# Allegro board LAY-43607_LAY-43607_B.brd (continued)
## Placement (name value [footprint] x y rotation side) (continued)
R737  -  [RC0402_25]  104.58 22.62 0 top
R739  -  [RC0402_25]  20.79 77.81 90 top
R742  -  [RC0402_25]  26.4 76.47 180 top
R743  -  [RC0402_25]  93.7 58.84 90 bottom
R744  -  [RC0402_25]  99.51 62.01 0 top
R745  -  [RC0402_25]  105.19 82.44 0 bottom
R748  -  [RC0402_25]  87.49 91.71 90 bottom
R749  -  [RC0402_25]  88.38 91.71 90 bottom
R750  -  [RC0402_25]  89.59 86.07 270 bottom
R751  -  [RC0402_25]  88.71 86.07 270 bottom
R752  -  [RC0402_25]  90.22 103.93 90 bottom
R753  -  [RC0402_25]  90.22 102.06 270 bottom
R754  -  [RC0402_25]  90.73 91.78 90 bottom
R755  -  [RC0402_25]  91.62 91.78 90 bottom
R756  -  [RC0402_25]  91.44 86.07 270 bottom
R757  -  [RC0402_25]  90.47 86.07 270 bottom
R758  -  [RC0402_25]  87.86 86.06 270 bottom
R775  -  [RC0402_25]  20.74 62.29 90 top
R776  -  [RC0402_25]  21.8 62.32 90 top
R777  -  [RC0402_25]  21.52 68.81 0 top
R778  -  [RC0402_25]  21.57 67.97 0 top
R781  0  [RC0402_25]  32.07 68.29 0 top
R782  0  [RC0402_25]  32.07 67.36 0 top
R783  0  [RC0402_25]  32.07 66.49 0 top
R784  0  [RC0402_25]  32.07 65.63 0 top
R785  0  [RC0402_25]  33.34 64.53 0 top
R786  0  [RC0402_25]  33.34 63.64 0 top
R787  0  [RC0402_25]  28.39 59.72 0 top
R788  0  [RC0402_25]  28.39 58.83 0 top
R789  0  [RC0402_25]  33.34 62.65 0 top
R790  0  [RC0402_25]  33.34 61.76 0 top
R791  0  [RC0402_25]  25.17 60.68 270 top
R792  0  [RC0402_25]  24.33 60.7 270 top
R793  -  [RC0402_25]  100.7 85.84 90 bottom
R798  0  [RC0402_25]  21.91 51.21 90 top
R801  4.7K  [RC0402_25]  38.36 37.25 270 bottom
R803  4.7K  [RC0402_25]  37.2 37.23 90 bottom
R804  4.7K  [RC0402_25]  37.2 37.23 90 top
R805  4.7K  [RC0402_25]  38.36 37.25 90 top
R806  0  [RC0402_25]  38.44 39.49 270 top
R809  -  [RC0402_25]  103.08 24.66 90 bottom
R810  4.7K  [RC0402_25]  114.99 24.17 180 top
R811  4.7K  [RC0402_25]  103.01 32.4 90 bottom
R812  -  [RC0402_25]  111.12 13.34 0 bottom
R813  -  [RC0402_25]  111.12 14.61 0 bottom
R814  -  [RC0402_25]  83.43 45.81 0 bottom
R815  4.7K  [RC0402_25]  85.96 42.47 0 bottom
R816  -  [RC0402_25]  85.96 39.43 0 bottom
R817  4.7K  [RC0402_25]  85.96 40.44 0 bottom
R818  -  [RC0402_25]  85.96 41.46 0 bottom
R819  -  [RC0402_25]  50.69 61.43 90 top
R823  -  [RC0402_25]  52.18 62.37 180 top
R824  4.7K  [RC0402_25]  52.69 62.88 90 top
R825  -  [RC0402_25]  123.96 29.18 180 bottom
R828  -  [RC0402_25]  75.58 112.72 270 top
R829  -  [RC0402_25]  74.31 111.09 270 top
R830  -  [RC0402_25]  82.76 111.14 270 top
R831  -  [RC0402_25]  81.09 112.72 270 top
R832  -  [RC0402_25]  79.13 111.27 270 top
R833  -  [RC0402_25]  77.94 111.19 270 top
R834  -  [RC0402_25]  76.74 112.72 270 top
R837  0  [RC0402_25]  118.1 12.95 0 top
R840  -  [RC0402_25]  121.65 14.8 90 top
R841  -  [RC0402_25]  118.1 13.81 0 top
R843  -  [RC0402_25]  120.79 14.83 270 top
R849  -  [RC0402_25]  124.83 12.72 0 top
R850  -  [RC0402_25]  124.83 13.61 0 top
R851  -  [RC0402_25]  104.92 76.08 180 bottom
R852  -  [RC0402_25]  108.98 76.21 0 bottom
R853  -  [RC0402_25]  104.79 72.65 180 bottom
R854  -  [RC0402_25]  108.98 72.65 0 bottom
R855  -  [RC0402_25]  106.54 62.63 90 bottom
R856  -  [RC0402_25]  107.43 62.63 90 bottom
R857  -  [RC0402_25]  108.87 63.17 0 bottom
R858  -  [RC0402_25]  104.67 65.12 180 bottom
R859  -  [RC0402_25]  84.57 96.08 90 bottom
R860  -  [RC0402_25]  86.8 96.16 90 bottom
R861  -  [RC0402_25]  81.39 95.98 90 bottom
R862  -  [RC0402_25]  83.68 95.98 90 bottom
R863  -  [RC0201]  58.57 47 180 bottom
R864  -  [RC0402_25]  43.8 61.23 180 top
R865  10K  [RC0402_25]  20.25 57.95 180 bottom
R866  -  [RC0402_25]  20.76 59.35 90 bottom
R867  -  [RC0402_25]  46.8 65.56 90 top
R868  -  [RC0402_25]  45.9 62.52 180 top
R869  -  [RC0402_25]  90.28 112.54 270 bottom
R870  -  [RC0402_25]  48.75 58.31 180 top
R871  -  [RC0402_25]  48.75 59.33 180 top
R872  -  [RC0402_25]  48.25 58.82 90 bottom
R873  -  [RC0402_25]  83.43 41.62 0 bottom
R874  -  [RC0402_25]  48.75 60.22 180 top
R875  -  [RC0402_25]  48.75 61.1 180 top
R878  -  [RC0402_25]  103.16 87.16 270 bottom
R879  1.0K  [RC0402_25]  106.03 99.03 0 top
R880  -  [RC0402_25]  104 87.19 270 bottom
R881  17.4K  [RC0402_25]  103.13 92.07 90 top
R882  100K  [RC0402_25]  104.79 90.19 180 bottom
R883  -  [RC0402_25]  79.42 58.64 90 top
R885  -  [RC0402_25]  100.57 74.49 0 top
R886  -  [RC0402_25]  117.23 83.66 0 top
R887  0  [RC0402_25]  125.89 41.98 180 top
R888  -  [RC0402_25]  123.18 53.99 180 top
R889  -  [RC0402_25]  123.18 54.88 0 top
R890  -  [RES4_7P1X6P9_SM]  102.73 45.36 180 bottom
R893  0  [RC0402_25]  130.3 39.02 270 bottom
R894  0  [RC0402_25]  127.87 45.36 0 top
R895  0  [RC0402_25]  127.66 39.04 270 bottom
R896  0  [RC0402_25]  127.87 44.21 0 top
R897  0  [RC0402_25]  129.46 39.02 270 bottom
R898  0  [RC0402_25]  128.5 39.04 270 bottom
R899  0  [RC0402_25]  128.38 47.01 270 top
R900  -  [RC0402_25]  115.4 72.22 0 top
R901  -  [RC0402_25]  111.72 72.7 180 bottom
R902  -  [RC0402_25]  115.46 73.9 180 top
R903  -  [RC0402_25]  120.15 73.75 90 top
R904  0  [RC0402_25]  115.38 71.36 0 bottom
R905  -  [RC0402_25]  117.41 73.8 90 top
R906  -  [RC0402_25]  120.98 73.78 270 bottom
R907  -  [RC0402_25]  120.99 73.77 90 top
R908  -  [RC0402_25]  111.12 3.17 0 bottom
R909  -  [RC0402_25]  111.12 4.44 0 bottom
R910  -  [RC0402_25]  111.12 5.71 0 bottom
R911  -  [RC0402_25]  111.12 6.98 0 bottom
R912  -  [RC0402_25]  111.12 8.26 0 bottom
R913  -  [RC0402_25]  111.12 9.53 0 bottom
R914  -  [RC0402_25]  111.12 10.8 0 bottom
R915  -  [RC0402_25]  111.12 12.07 0 bottom
R916  -  [RC1206_OV]  100.59 117.31 270 bottom
R917  -  [RC1206_OV]  88.78 117.24 270 top
R920  0  [RC0402_25]  127.19 26.15 0 bottom
R921  -  [RC1206_OV]  114.92 10.56 90 bottom
R922  330 OHM  [RC0402_25]  36.38 46.84 270 top
R923  330 OHM  [RC0402_25]  40.9 35.4 180 top
R924  -  [RC0402_25]  98.21 70.6 270 bottom
R925  -  [RC0402_25]  115.28 100.88 270 bottom
R927  -  [RC0402_25]  71.36 70.25 90 top
R928  -  [RC0402_25]  77.56 84.32 180 top
R929  -  [RC0402_25]  72.25 70.22 90 bottom
R930  -  [RC0402_25]  72.25 70.22 270 top
R931  -  [RC0402_25]  77 78.91 270 bottom
R932  -  [RC0402_25]  69.96 84.13 90 top
R933  -  [RC0402_25]  69.07 84.13 90 top
R934  -  [RC0402_25]  70.47 70.25 90 top
R935  -  [RC0402_25]  69.45 70.25 90 top
R936  -  [RC0402_25]  75.3 70.27 90 top
R937  -  [RC0402_25]  73.52 84.13 270 top
R938  0  [RC0402_25]  70.47 70.25 270 bottom
R939  0  [RC0402_25]  77.56 83.3 0 top
R940  -  [RC0402_25]  99.35 66.46 90 top
R941  0  [RC0402_25]  76.57 102.96 90 top
R942  0  [RC0402_25]  75.73 102.96 90 top
R943  -  [RC0402_25]  65.14 73.55 180 top
R944  -  [RC0402_25]  122.51 14.8 270 top
R945  -  [RC0402_25]  35.83 65.28 180 top
R946  4.7K  [RC0402_25]  35.32 65.79 270 top
R947  0  [RC0402_25]  94.73 68.37 270 top
R948  -  [RC0402_25]  114.41 100.37 270 bottom
R953  0  [RC0402_25]  88.23 60.09 0 bottom
R954  -  [RC0402_25]  51.93 10.18 270 bottom
R955  -  [RC0402_25]  52.84 10.18 90 bottom
R956  -  [RC0402_25]  41.02 9.79 270 bottom
R957  -  [RC0402_25]  41.87 9.8 90 bottom
R958  -  [RC0402_25]  64.63 8.78 90 bottom
R959  -  [RC0402_25]  63.74 8.77 270 bottom
R960  -  [RC0402_25]  86.45 9.06 270 bottom
R961  -  [RC0402_25]  87.28 9.03 90 bottom
R962  -  [RC0402_25]  76.15 8.77 90 bottom
R963  -  [RC0402_25]  75.3 8.77 270 bottom
R964  -  [RC0201]  64.63 40.14 90 bottom
S1  -  [SW_DIP20_10POS_SM]  107.81 8.91 90 top
SW6  -  [SW2_4P45_4X3_SM]  129.68 36.9 180 top
TP94  5006  [TP_TH_063]  129.86 50.69 0 top
TP95  5006  [TP_TH_063]  88.5 82.19 0 top
TP116  -  [TP_PTH]  120.58 54.02 0 top
TP117  -  [TP_PTH]  121.4 55.9 0 top
TP126  -  [TPAD_020]  91.3 45.23 0 top
TP127  -  [TPAD_020]  19.38 77.73 0 top
TP128  -  [TP_PTH]  38.24 44.49 180 bottom
TP129  -  [TP_PTH]  38.24 46.65 180 bottom
TP130  -  [TP_PTH]  38.24 48.81 180 bottom
TP139  -  [TP_PTH]  40.65 30.17 0 top
TP140  -  [TP_PTH]  36.9 30.92 0 top
TP141  -  [TP_PTH]  38.93 31.37 0 top
TP142  -  [TPAD_020]  117.44 24.03 0 top
TVS1  SESD0402X1BN  [DIODE_BIDIR_0402]  77.73 116.76 180 top
U1  -  [QFN16_0P5_3X3_EP_4MP]  113.52 83.58 270 top
U14  -  [BGA780_0P8_23X23MM]  64.62 45.4 270 top
U15  -  [BGA96_0P8_8P1X14P1]  92.84 12.11 0 top
U16  MT40A512M16  [BGA96_0P8_8P1X14P1]  81.36 12.11 0 top
U17  -  [BGA96_0P8_8P1X14P1]  58.4 12.11 0 top
U18  -  [BGA96_0P8_8P1X14P1]  46.92 12.11 0 top
U24  -  [SOT-363_0P65_SMT]  90.26 59.29 0 top
U28  -  [SO8_1P27_4X5]  98.06 58.74 0 top
U35  74LVC2T45DC  [SSOP8_DCU]  73.65 99.08 180 top
U36  -  [SSOP8_DCU]  82.54 99.08 180 top
U37  -  [SSOP8_DCU]  76.44 99.08 0 top
U38  -  [XSON7_0P5_2P2X1P2]  76.13 110.35 90 top
U39  -  [XSON7_0P5_2P2X1P2]  80.96 110.38 90 top
U40  -  [WLCSP12_0P4_1P38X1P68MM_SMDP]  111.59 92.47 180 top
U42  PRTR5V0U2AX  [SOT143B]  103.34 111.93 90 bottom
U44  -  [XSON10_0P5_1P1X2P6MM]  96.17 95.67 90 bottom
U50  -  [QFN40_0P5_6X6_2P6EP]  26.83 65.09 270 top
U54  -  [WLCSP6_0P5_0P98X1P48]  118.58 19.7 0 top
U55  -  [SOT-363_0P65_SMT]  121.17 22.98 0 bottom
U56  -  [SC70-5]  121.22 25.76 90 top
U58  74AUP1G09GW  [SC70-5]  17.56 57.29 270 bottom
U60  -  [SC70-5]  17.61 59.91 270 bottom
U62  -  [SC70-5]  46.61 64.87 90 bottom
U114  -  [SC70-5]  121.22 25.76 90 bottom
U123  -  [AQFN138_0P65_12X12_EP]  41.64 76.6 180 top
U522  -  [VFBGA63_0P8_9X11]  109.84 23.39 270 bottom
U523  PCF2129AT  [SO20_1P27_7P6X12P95]  22.16 78.38 0 bottom
U524  -  [SO8_1P27_4X5]  102.48 81.78 0 top
U525  -  [TSSOP16]  89.2 88.81 90 top
U527  -  [SC70-5]  89.39 89.29 270 bottom
U530  -  [SC70-5]  100.66 87.05 180 top
U532  -  [SO16W]  107.74 28.62 0 top
U533  -  [SC70-5]  121.14 28.52 90 bottom
U534  -  [SC70-5]  120.89 17.8 180 bottom
U535  -  [SC70-5]  100.44 70.25 270 bottom
U536  -  [QFN20_3X3MM_B]  121.55 11.52 90 top
U537  PRTR5V0U2AX  [SOT143B]  118.98 8.78 270 bottom
U538  -  [TSSOP8_A]  106.82 64.14 180 top
U539  -  [SSOP8_DCU]  79.44 99.08 180 top
U540  -  [SSOP8_DCU]  85.53 99.1 180 top
U543  PUSB3AB6  [XSON7_0P5_2P2X1P2]  16.99 108.42 180 bottom
U544  PUSB3AB6  [XSON7_0P5_2P2X1P2]  17.03 98.26 180 bottom
U545  PUSB3AB6  [XSON7_0P5_2P2X1P2]  17.05 93.19 180 bottom
U546  -  [SC70-5]  44.82 61.87 270 bottom
U547  -  [SC70-5]  100.44 67.45 90 bottom
U548  -  [XSON_8P]  87.21 111.88 90 top
U549  -  [SSOP8_DCU]  100.62 64.07 270 top
U550  NX5P3090UK  [WLCSP12_0P4_1P38X1P68MM_SMDP]  104.89 92.17 180 top
U551  -  [SC70-5]  103.29 87.06 0 top
U552  PRTR5V0U2AX  [SOT143B]  99.22 99.18 270 top
U553  -  [XSON10_0P5_1P1X2P6MM]  100.65 95.67 90 bottom
U554  -  [UQFN10_0P4_1P45X1P85]  102.6 77.84 90 top
U555  -  [SSOP8_DCU]  100.56 74.01 0 bottom
U557  -  [BGA42_0P8_5X6]  119.75 45.36 270 top
U558  INA220AIDGST  [MSOP_10_0P5_3X3]  128.26 55.01 180 top
U560  -  [QFN24_4X4MM_4EP]  118.73 69.11 0 top
U561  -  [QFN56_0P5_8P1X8P1_EP5P1]  70.85 77.51 0 top
U562  -  [SC70-5]  121.14 28.52 90 top
U563  PUSB3AB6  [XSON7_0P5_2P2X1P2]  126.98 13.72 180 top
U564  PUSB3AB6  [XSON7_0P5_2P2X1P2]  125.87 22.9 180 bottom
U565  -  [BGA96_0P8_8P1X14P1]  69.88 12.11 0 top
U566  -  [SC70-5]  92.57 66.06 270 top

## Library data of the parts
BH5-BH10 = MOUNT_HOLE
BT3 = BATTERY_SKT_3V
C5 C27 C119 C120 C180 C288 C1331 C1337 C1338 C1346 = CAP_POL
C12 C14 C18-C22 C24-C26 C28 C30-C32 C36 C113 C125 C128 C151 C155 C159 C161 C166-C176 C230 C234 C235 C239 C240 C244 C245 C249 C254 C275 C279-C287 C289 C296 C297 C386 C388 C410 C431 C437 C457 C459 C1271-C1273 C1277 C1280 C1298 C1304 C1310 C1313 C1320 C1323 C1324 C1329 C1330 C1332 C1333 C1339-C1345 C1347 C1348 C1354 C1357 C1360 C1434-C1436 C1438 C1439 C1441 C1454-C1463 C1467-C1472 C1475 C1476 C1481 C1489-C1494 C1520 C1521 C1524 C1525 C1530 C1531 C1533 C1534 C1536 C1537 C1540 C1545 C1547-C1550 C1581 C1587 = CAP_NP
C29 = CAP_NP: tolerance: 20%; room: 12VIN
C114-C116 C118 C127 C252 C277 C1586 = CAP_NP: room: VDD_GVDD_PS
C122 C1139-C1142 C1150 C1151 C1156 C1157 = CAP_NP: tolerance: 5%
C126 C231 C233 C236 C238 C242 C243 C246 C248 C369 C408 C409 C438 C488 C668 C669 C847-C855 C1000 C1001 C1003-C1005 C1007-C1011 C1013 C1015-C1019 C1103 C1248 C1249 C1251 C1253 C1255 C1256 C1258 C1259 C1295 C1296 C1299 C1302 C1305 C1334 C1335 C1352 C1353 C1355 C1356 C1358 C1359 C1361 C1382 C1384 C1385 C1406 C1408 C1409 C1430 C1432 C1433 C1443-C1446 C1450-C1453 C1464 C1495 C1523 C1526 C1532 C1535 C1538 C1542 C1544 C1551-C1554 C1556 C1577 C1579 = CAP_NP: tolerance: 10%
C148 C149 C152 C153 C156 C157 C160 C162-C165 C181-C188 C193-C202 C206-C213 C219-C229 C258-C271 C290-C295 C298 C299 C301 C303-C324 C328 C329 C332-C334 C336-C338 C364-C367 C374 C375 C383 C384 C517-C524 C933-C936 C1349-C1351 C1362-C1380 C1386-C1404 C1410-C1428 C1557-C1575 = CAP_NP: Tolerance: 10%; User Part Number: 150-80059; tolerance: 10%
C189-C191 C203-C205 C214-C218 = CAP_NP: Tolerance: 10%; User Part Number: 150-75466; tolerance: 10%
C232 C237 C241 C247 = CAP_NP: Tolerance: TOLERANCE; User Part Number: 150-79701
C278 = CAP_NP: room: LED
C300 C302 C330 = CAP_NP: tolerance: 20%
C402 C403 C1584 C1585 = CAP_NP: room: DDR_DIMM
C449-C454 C463 C464 C487 C489 C492 C493 C497 C498 C905 C1297 C1306-C1309 C1314-C1319 C1325-C1328 C1555 C1582 C1583 = CAP_NP: Tolerance: TOLERANCE; User Part Number: 150-80059
C458 C1321 = CAP_NP: room: USB2
C460 C1322 = CAP_NP: room: VTT_VREF_PS
C693 C787-C789 C798 C1020 C1274-C1276 C1278 C1437 C1440 C1442 = CAP_NP: tolerance: 5%; room: RS232
C729 C772 C1021-C1024 C1143-C1149 C1152-C1155 = CAP_NP: tolerance: 10%; room: PEX_SLOTS123_REFCLK
C1104 = CAP_NP: room: PS_DDR1_2_VTT
C1166 C1168 C1293 C1294 C1546 = CAP_NP: Tolerance: TOLERANCE; User Part Number: 150-79474
C1174 C1282 C1283 C1447-C1449 C1465 C1466 = CAP_NP: tolerance: 10%; room: SDHC
D2 D4 D508 D510 D511 = LED
D6 = ZDIODE
D509 = LED_QUAD_GRN
F2 = FUSE_RST
FL2 FL31 FL32 = EMIFILTER_CC
FL3-FL5 FL7 FL8 FL28-FL30 = NFM18PC225B1A3: room: DUT_CLOSE
FL18 FL19 FL22 = NFM18PC225B1A3
J1 = DC_POWER_JACK_063BH
J8 J9 J11-J14 J72 J74 J75 = CONN_HDR_2X1
J15 = CONN_HDR_5X2
J46 J52 = CON_67_FEMALE_RA
J55 = CON8_SDCARD_DETECT
J56 J57 J66 = CONN_HDR_8X1
J58 = ZX62RD-AB-5P8_USB_MICROAB
J60 = CONN_HDR_6X1
J63-J65 = CONN_HDR_3X1
J67 = CONN_HDR_10X2
J70 = GSB311231HR_USB18P
J73 = HDR-1X4
L2 = CHOKE_4P
L9 L516 L531-L533 L535-L537 = INDUCTOR
L11 L514 = NFE31P: tolerance: 50%
L56 = INDUCTOR_FERRITE: tolerance: 25%
L515 = INDUCTOR: tolerance: 20%
P1 P2 = RJ45_MAG_2X1_LED
Q3 = MOSFET_N
Q4 = NMOSFET_3P_ESD_DIODE
R5 R10 = RES: room: DDR_PS
R6 R15 R887 R899 R904 R938 R939 = RES: tolerance: 5%; room: VDD_GVDD_PS
R7 R11 R13 R33 R36 R52 R55 R56 R59 R60 R64 R66 R67 R82-R84 R91-R98 R100-R107 R111-R138 R140-R144 R157 R158 R160 R161 R167-R172 R177 R185-R187 R191 R192 R202-R205 R228 R239 R241-R245 R248 R249 R257-R261 R277 R298 R299 R301-R305 R355 R409 R412 R473 R474 R558 R560 R643-R659 R661-R663 R666-R669 R737 R739 R742-R745 R748-R758 R775-R778 R793 R801 R803-R805 R809-R819 R823-R825 R828-R834 R840 R841 R843 R849-R875 R878-R883 R885 R886 R888 R889 R900-R903 R905-R917 R921-R925 R927-R937 R940 R943-R946 R948 R954-R964 = RES
R25 R62 R188 R255 R401 R471 R660 R781-R792 R798 R806 R837 R893-R898 R920 R941 R942 R947 R953 = RES: signal model: RES_RC0402_25_DISCRETE_0.4MM__7_0
R890 = RES_4PIN
S1 = SW_DIP-10
SW6 = SW2P_SPST
TP94 TP95 = TEST_POINT: room: CS
TP116 TP117 TP126-TP130 TP139-TP142 = TestLoop
TVS1 = DIODE_TVS_BIDIR
U1 = LT8609S_16P_EP
U14 = LS1043_1046_SS
U15-U18 U565 = MT40A512M16JY_BGA96
U24 = 74AUP2G07GW
U28 = SA56004ED_SO8
U35-U37 U539 U540 U549 U555 = 74LVC2T45DC_8P
U38 U39 U543-U545 U563 U564 = PUSB3AB6
U40 U550 = NX5P3090UK_WLCSP12
U42 U537 U552 = PRTR5V0U2AX: room: USB1
U44 U553 = DIODE_ESD_4CH_PUSB3AB4
U50 = Si5332FD10253-GM2_QFN40
U54 = ADM8611_WLCSP_6P
U55 = 74AUP1G11GW
U56 U114 U527 U533 = 74AUP1G07GW
U58 U60 U62 U534 U546 U547 U562 = GATE_AND_SGL
U123 = VSC8514_QFN_138P_A
U522 = S34MS04G200BH_BGA63P
U523 = PCF2129AT_SO_20P: room: I2C1_CH3
U524 = CAT24C04_SO8
U525 = PCA9546_16P
U530 U535 U551 U566 = NC7SZ14
U532 = MT25QU512ABB8ESF_SO16W
U536 = CP2102N_QFN20
U538 = PCA9510ADP_8P
U548 = NTB0102_8P
U554 = NX3DV42GU_XQFN_10P_A
U557 = LTC7150_BGA42
U558 = INA220AIDGST: room: I2C1_CH2
U560 = LT8642SEV_LQFN24
U561 = PC33PF8100A0ES_QFN56

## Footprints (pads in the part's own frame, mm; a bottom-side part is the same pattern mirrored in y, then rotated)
8X10P8
  rect 4.191x2.21 smd: 1(-3.645,0) 2(3.645,0)
AQFN138_0P65_12X12_EP
  rect 4.902x4.902 smd: 139(-0.325,0.65)
  round 0.737 smd: A1(5.45,-5.45) A4(5.45,5.45) A5(-5.45,5.45) A6(-5.45,-5.45)
  round 0.33 smd: A2(5.626,1.3) A3(5.626,1.95) A8(-0.325,-5.301) A9(0.325,-5.301) B1(4.976,-1.625) B2(4.976,-0.975) B3(4.976,0.325) B4(4.976,0.975) B5(4.976,1.625) B6(4.977,2.925) B8(4.976,4.225) B9(-5.627,3.575) B10(-5.627,2.925) B11(-5.627,0.975) B12(-5.627,0.325) B15(-2.6,-4.651) B16(-1.95,-4.651) B17(-1.3,-4.651) B20(1.3,-4.651) C1(4.326,-3.25) C2(4.326,-1.95) C4(4.326,-0.65) C5(4.326,0) C6(4.326,1.3) C7(4.326,1.95) C8(4.326,2.6) C9(4.326,3.25) C10(4.326,4.55) C11(4.225,5.302) C12(2.275,5.302) C13(1.625,5.302) C14(-4.977,4.55) C15(-4.977,3.9) C16(-4.977,3.25) C17(-4.977,2.6) C18(-4.977,1.3) C19(-4.977,0.65) C20(-4.977,-0.65) C21(-4.977,-1.95) C22(-4.977,-2.6) C23(-4.977,-3.25) C24(-4.225,-4.001) C25(-3.575,-4.001) C26(-2.925,-4.001) C27(-2.275,-4.001) C30(-0.325,-4.001) C34(2.275,-4.001) C35(2.925,-4.001) C36(4.225,-4.001) D1(3.676,-2.275) D2(3.676,-1.625) D3(3.676,-0.975) D4(3.676,-0.325) D5(3.676,0.325) D6(3.676,0.975) D7(3.676,1.625) D10(3.676,4.225) D11(2.6,4.652) D12(1.95,4.652) D13(0.65,4.652) D14(0,4.652) D15(-1.3,4.652) D16(-1.95,4.652) D17(-2.6,4.652) D18(-3.25,4.652) D19(-4.327,4.225) D20(-4.327,3.575) D22(-4.327,2.275) D23(-4.327,1.625) D24(-4.327,0.975) D25(-4.327,0.325) D26(-4.327,-0.325) D28(-4.327,-1.625) D29(-3.9,-3.351) D31(-2.6,-3.351) D32(1.3,-3.351) D34(2.6,-3.351) E1(3.026,-2.6) E2(3.026,-1.3) E5(3.026,0.65) E6(3.026,1.3) E7(3.026,1.95) E8(3.026,2.6) E9(3.026,3.25) E10(2.925,4.002) E12(1.625,4.002) E13(0.975,4.002) E15(-0.325,4.002) E17(-1.625,4.002) E19(-3.575,4.002) E21(-3.677,2.6) E22(-3.677,1.95) E23(-3.677,1.3) E24(-3.677,0.65) E25(-3.677,0) E27(-3.677,-1.3) E28(-3.677,-1.95) E29(-2.925,-2.701) E30(-2.275,-2.701) E31(-1.625,-2.701) E32(-0.975,-2.701) E33(-0.325,-2.701) E34(0.325,-2.701) E35(0.975,-2.701) E36(1.625,-2.701) E37(2.275,-2.701)
  oval 0.457x0.305 smd: A7(-0.975,-5.301) A10(0.975,-5.301) B19(0.65,-4.651) C28(-1.625,-4.001) C29(-0.975,-4.001) C31(0.325,-4.001) C32(0.975,-4.001) C33(1.625,-4.001) D35(3.25,-3.351) E11(2.275,4.002) E14(0.325,4.002) E16(-0.975,4.002)
  oval 0.305x0.457 smd: B7(4.976,3.575) C3(4.326,-1.3) D8(3.676,2.275) D9(3.676,2.925) D21(-4.327,2.925) E3(3.026,-0.65) E4(3.026,0) E20(-3.677,3.25)
  oval 0.305x0.584 smd: B13(-5.627,-0.975) B14(-5.627,-2.275) D27(-4.327,-0.975) E26(-3.677,-0.65)
  oval 0.584x0.305 smd: B18(-0.65,-4.651) D30(-3.25,-3.351) D33(1.95,-3.351) E18(-2.275,4.002)
BGA42_0P8_5X6
  round 0.406 smd: A1(-2,2.4) A2(-1.2,2.4) A3(-0.4,2.4) A4(0.4,2.4) A5(1.2,2.4) A6(2,2.4) B1(-2,1.6) B2(-1.2,1.6) B3(-0.4,1.6) B4(0.4,1.6) B5(1.2,1.6) B6(2,1.6) C1(-2,0.8) C2(-1.2,0.8) C3(-0.4,0.8) C4(0.4,0.8) C5(1.2,0.8) C6(2,0.8) D1(-2,0) D2(-1.2,0) D3(-0.4,0) D4(0.4,0) D5(1.2,0) D6(2,0) E1(-2,-0.8) E2(-1.2,-0.8) E3(-0.4,-0.8) E4(0.4,-0.8) E5(1.2,-0.8) E6(2,-0.8) F1(-2,-1.6) F2(-1.2,-1.6) F3(-0.4,-1.6) F4(0.4,-1.6) F5(1.2,-1.6) F6(2,-1.6) G1(-2,-2.4) G2(-1.2,-2.4) G3(-0.4,-2.4) G4(0.4,-2.4) G5(1.2,-2.4) G6(2,-2.4)
BGA96_0P8_8P1X14P1
  round 0.432 smd: A1(-3.2,6) A2(-2.4,6) A3(-1.6,6) A7(1.6,6) A8(2.4,6) A9(3.2,6) B1(-3.2,5.2) B2(-2.4,5.2) B3(-1.6,5.2) B7(1.6,5.2) B8(2.4,5.2) B9(3.2,5.2) C1(-3.2,4.4) C2(-2.4,4.4) C3(-1.6,4.4) C7(1.6,4.4) C8(2.4,4.4) C9(3.2,4.4) D1(-3.2,3.6) D2(-2.4,3.6) D3(-1.6,3.6) D7(1.6,3.6) D8(2.4,3.6) D9(3.2,3.6) E1(-3.2,2.8) E2(-2.4,2.8) E3(-1.6,2.8) E7(1.6,2.8) E8(2.4,2.8) E9(3.2,2.8) F1(-3.2,2) F2(-2.4,2) F3(-1.6,2) F7(1.6,2) F8(2.4,2) F9(3.2,2) G1(-3.2,1.2) G2(-2.4,1.2) G3(-1.6,1.2) G7(1.6,1.2) G8(2.4,1.2) G9(3.2,1.2) H1(-3.2,0.4) H2(-2.4,0.4) H3(-1.6,0.4) H7(1.6,0.4) H8(2.4,0.4) H9(3.2,0.4) J1(-3.2,-0.4) J2(-2.4,-0.4) J3(-1.6,-0.4) J7(1.6,-0.4) J8(2.4,-0.4) J9(3.2,-0.4) K1(-3.2,-1.2) K2(-2.4,-1.2) K3(-1.6,-1.2) K7(1.6,-1.2) K8(2.4,-1.2) K9(3.2,-1.2) L1(-3.2,-2) L2(-2.4,-2) L3(-1.6,-2) L7(1.6,-2) L8(2.4,-2) L9(3.2,-2) M1(-3.2,-2.8) M2(-2.4,-2.8) M3(-1.6,-2.8) M7(1.6,-2.8) M8(2.4,-2.8) M9(3.2,-2.8) N1(-3.2,-3.6) N2(-2.4,-3.6) N3(-1.6,-3.6) N7(1.6,-3.6) N8(2.4,-3.6) N9(3.2,-3.6) P1(-3.2,-4.4) P2(-2.4,-4.4) P3(-1.6,-4.4) P7(1.6,-4.4) P8(2.4,-4.4) P9(3.2,-4.4) R1(-3.2,-5.2) R2(-2.4,-5.2) R3(-1.6,-5.2) R7(1.6,-5.2) R8(2.4,-5.2) R9(3.2,-5.2) T1(-3.2,-6) T2(-2.4,-6) T3(-1.6,-6) T7(1.6,-6) T8(2.4,-6) T9(3.2,-6)
BGA780_0P8_23X23MM
  round 0.356 smd: A2(-10,10.8) A3(-9.2,10.8) A4(-8.4,10.8) A5(-7.6,10.8) A6(-6.8,10.8) A7(-6,10.8) A8(-5.2,10.8) A9(-4.4,10.8) A10(-3.6,10.8) A11(-2.8,10.8) A12(-2,10.8) A13(-1.2,10.8) A14(-0.4,10.8) A15(0.4,10.8) A16(1.2,10.8) A17(2,10.8) A18(2.8,10.8) A19(3.6,10.8) A20(4.4,10.8) A21(5.2,10.8) A22(6,10.8) A23(6.8,10.8) A24(7.6,10.8) A25(8.4,10.8) A26(9.2,10.8) A27(10,10.8) AA1(-10.8,-5.2) AA2(-10,-5.2) AA3(-9.2,-5.2) AA4(-8.4,-5.2) AA5(-7.6,-5.2) AA6(-6.8,-5.2) AA7(-6,-5.2) AA8(-5.2,-5.2) AA9(-4.4,-5.2) AA10(-3.6,-5.2) AA11(-2.8,-5.2) AA12(-2,-5.2) AA13(-1.2,-5.2) AA14(-0.4,-5.2) AA15(0.4,-5.2) AA16(1.2,-5.2) AA17(2,-5.2) AA18(2.8,-5.2) AA19(3.6,-5.2) AA20(4.4,-5.2) AA21(5.2,-5.2) AA22(6,-5.2) AA23(6.8,-5.2) AA24(7.6,-5.2) AA25(8.4,-5.2) AA26(9.2,-5.2) AA27(10,-5.2) AA28(10.8,-5.2) AB1(-10.8,-6) AB2(-10,-6) AB3(-9.2,-6) AB4(-8.4,-6) AB5(-7.6,-6) AB6(-6.8,-6) AB7(-6,-6) AB8(-5.2,-6) AB9(-4.4,-6) AB10(-3.6,-6) AB11(-2.8,-6) AB12(-2,-6) AB13(-1.2,-6) AB14(-0.4,-6) AB15(0.4,-6) AB16(1.2,-6) AB17(2,-6) AB18(2.8,-6) AB19(3.6,-6) AB20(4.4,-6) AB21(5.2,-6) AB22(6,-6) AB23(6.8,-6) AB24(7.6,-6) AB25(8.4,-6) AB26(9.2,-6) AB27(10,-6) AB28(10.8,-6) AC1(-10.8,-6.8) AC2(-10,-6.8) AC3(-9.2,-6.8) AC4(-8.4,-6.8) AC5(-7.6,-6.8) AC6(-6.8,-6.8) AC7(-6,-6.8) AC8(-5.2,-6.8) AC9(-4.4,-6.8) AC10(-3.6,-6.8) AC11(-2.8,-6.8) AC12(-2,-6.8) AC13(-1.2,-6.8) AC14(-0.4,-6.8) AC15(0.4,-6.8) AC16(1.2,-6.8) AC17(2,-6.8) AC18(2.8,-6.8) AC19(3.6,-6.8) AC20(4.4,-6.8) AC21(5.2,-6.8) AC22(6,-6.8) AC23(6.8,-6.8) AC24(7.6,-6.8) AC25(8.4,-6.8) AC26(9.2,-6.8) AC27(10,-6.8) AC28(10.8,-6.8) AD1(-10.8,-7.6) AD2(-10,-7.6) AD3(-9.2,-7.6) AD4(-8.4,-7.6) AD5(-7.6,-7.6) AD6(-6.8,-7.6) AD7(-6,-7.6) AD8(-5.2,-7.6) AD9(-4.4,-7.6) AD10(-3.6,-7.6) AD11(-2.8,-7.6) AD12(-2,-7.6) AD13(-1.2,-7.6) AD14(-0.4,-7.6) AD15(0.4,-7.6) AD16(1.2,-7.6) AD17(2,-7.6) AD18(2.8,-7.6) AD19(3.6,-7.6) AD20(4.4,-7.6) AD21(5.2,-7.6) AD22(6,-7.6) AD23(6.8,-7.6) AD24(7.6,-7.6) AD25(8.4,-7.6) AD26(9.2,-7.6) AD27(10,-7.6) AD28(10.8,-7.6) AE1(-10.8,-8.4) AE2(-10,-8.4) AE3(-9.2,-8.4) AE4(-8.4,-8.4) AE5(-7.6,-8.4) AE6(-6.8,-8.4) AE7(-6,-8.4) AE8(-5.2,-8.4) AE9(-4.4,-8.4) AE10(-3.6,-8.4) AE11(-2.8,-8.4) AE12(-2,-8.4) AE13(-1.2,-8.4) AE14(-0.4,-8.4) AE15(0.4,-8.4) AE16(1.2,-8.4) AE17(2,-8.4) AE18(2.8,-8.4) AE19(3.6,-8.4) AE20(4.4,-8.4) AE21(5.2,-8.4) AE22(6,-8.4) AE23(6.8,-8.4) AE24(7.6,-8.4) AE25(8.4,-8.4) AE26(9.2,-8.4) AE27(10,-8.4) AE28(10.8,-8.4) AF1(-10.8,-9.2) AF2(-10,-9.2) AF3(-9.2,-9.2) AF4(-8.4,-9.2) AF5(-7.6,-9.2) AF6(-6.8,-9.2) AF7(-6,-9.2) AF8(-5.2,-9.2) AF9(-4.4,-9.2) AF10(-3.6,-9.2) AF11(-2.8,-9.2) AF12(-2,-9.2) AF13(-1.2,-9.2) AF14(-0.4,-9.2) AF15(0.4,-9.2) AF16(1.2,-9.2) AF17(2,-9.2) AF18(2.8,-9.2) AF19(3.6,-9.2) AF20(4.4,-9.2) AF21(5.2,-9.2) AF22(6,-9.2) AF23(6.8,-9.2) AF24(7.6,-9.2) AF25(8.4,-9.2) AF26(9.2,-9.2) AF27(10,-9.2) AF28(10.8,-9.2) AG1(-10.8,-10) AG2(-10,-10) AG3(-9.2,-10) AG4(-8.4,-10) AG5(-7.6,-10) AG6(-6.8,-10) AG7(-6,-10) AG8(-5.2,-10) AG9(-4.4,-10) AG10(-3.6,-10) AG11(-2.8,-10) AG12(-2,-10) AG13(-1.2,-10) AG14(-0.4,-10) AG15(0.4,-10) AG16(1.2,-10) AG17(2,-10) AG18(2.8,-10) AG19(3.6,-10) AG20(4.4,-10) AG21(5.2,-10) AG22(6,-10) AG23(6.8,-10) AG24(7.6,-10) AG25(8.4,-10) AG26(9.2,-10) AG27(10,-10) AG28(10.8,-10) AH2(-10,-10.8) AH3(-9.2,-10.8) AH4(-8.4,-10.8) AH5(-7.6,-10.8) AH6(-6.8,-10.8) AH7(-6,-10.8) AH8(-5.2,-10.8) AH9(-4.4,-10.8) AH10(-3.6,-10.8) AH11(-2.8,-10.8) AH12(-2,-10.8) AH13(-1.2,-10.8) AH14(-0.4,-10.8) AH15(0.4,-10.8) AH16(1.2,-10.8) AH17(2,-10.8) AH18(2.8,-10.8) AH19(3.6,-10.8) AH20(4.4,-10.8) AH21(5.2,-10.8) AH22(6,-10.8) AH23(6.8,-10.8) AH24(7.6,-10.8) AH25(8.4,-10.8) AH26(9.2,-10.8) AH27(10,-10.8) B1(-10.8,10) B2(-10,10) B3(-9.2,10) B4(-8.4,10) B5(-7.6,10) B6(-6.8,10) B7(-6,10) B8(-5.2,10) B9(-4.4,10) B10(-3.6,10) B11(-2.8,10) B12(-2,10) B13(-1.2,10) B14(-0.4,10) B15(0.4,10) B16(1.2,10) B17(2,10) B18(2.8,10) B19(3.6,10) B20(4.4,10) B21(5.2,10) B22(6,10) B23(6.8,10) B24(7.6,10) B25(8.4,10) B26(9.2,10) B27(10,10) B28(10.8,10) C1(-10.8,9.2) C2(-10,9.2) C3(-9.2,9.2) C4(-8.4,9.2) C5(-7.6,9.2) C6(-6.8,9.2) C7(-6,9.2) C8(-5.2,9.2) C9(-4.4,9.2) C10(-3.6,9.2) C11(-2.8,9.2) C12(-2,9.2) C13(-1.2,9.2) C14(-0.4,9.2) C15(0.4,9.2) C16(1.2,9.2) C17(2,9.2) C18(2.8,9.2) C19(3.6,9.2) C20(4.4,9.2) C21(5.2,9.2) C22(6,9.2) C23(6.8,9.2) C24(7.6,9.2) C25(8.4,9.2) C26(9.2,9.2) C27(10,9.2) C28(10.8,9.2) D1(-10.8,8.4) D2(-10,8.4) D3(-9.2,8.4) D4(-8.4,8.4) D5(-7.6,8.4) D6(-6.8,8.4) D7(-6,8.4) D8(-5.2,8.4) D9(-4.4,8.4) D10(-3.6,8.4) D11(-2.8,8.4) D12(-2,8.4) D13(-1.2,8.4) D14(-0.4,8.4) D15(0.4,8.4) D16(1.2,8.4) D17(2,8.4) D18(2.8,8.4) D19(3.6,8.4) D20(4.4,8.4) D21(5.2,8.4) D22(6,8.4) D23(6.8,8.4) D24(7.6,8.4) D25(8.4,8.4) D26(9.2,8.4) D27(10,8.4) D28(10.8,8.4) E1(-10.8,7.6) E2(-10,7.6) E3(-9.2,7.6) E4(-8.4,7.6) E5(-7.6,7.6) E6(-6.8,7.6) E7(-6,7.6) E8(-5.2,7.6) E9(-4.4,7.6) E10(-3.6,7.6) E11(-2.8,7.6) E12(-2,7.6) E13(-1.2,7.6) E14(-0.4,7.6) E15(0.4,7.6) E16(1.2,7.6) E17(2,7.6) E18(2.8,7.6) E19(3.6,7.6) E20(4.4,7.6) E21(5.2,7.6) E22(6,7.6) E23(6.8,7.6) E24(7.6,7.6) E25(8.4,7.6) E26(9.2,7.6) E27(10,7.6) E28(10.8,7.6) F1(-10.8,6.8) F2(-10,6.8) F3(-9.2,6.8) F4(-8.4,6.8) F5(-7.6,6.8) F6(-6.8,6.8) F7(-6,6.8) F8(-5.2,6.8) F9(-4.4,6.8) F10(-3.6,6.8) F11(-2.8,6.8) F12(-2,6.8) F13(-1.2,6.8) F14(-0.4,6.8) F15(0.4,6.8) F16(1.2,6.8) F17(2,6.8) F18(2.8,6.8) F19(3.6,6.8) F20(4.4,6.8) F21(5.2,6.8) F22(6,6.8) F23(6.8,6.8) F24(7.6,6.8) F25(8.4,6.8) F26(9.2,6.8) F27(10,6.8) F28(10.8,6.8) G1(-10.8,6) G2(-10,6) G3(-9.2,6) G4(-8.4,6) G5(-7.6,6) G6(-6.8,6) G7(-6,6) G8(-5.2,6) G9(-4.4,6) G10(-3.6,6) G11(-2.8,6) G12(-2,6) G13(-1.2,6) G14(-0.4,6) G15(0.4,6) G16(1.2,6) G17(2,6) G18(2.8,6) G19(3.6,6) G20(4.4,6) G21(5.2,6) G22(6,6) G23(6.8,6) G24(7.6,6) G25(8.4,6) G26(9.2,6) G27(10,6) G28(10.8,6) H1(-10.8,5.2) H2(-10,5.2) H3(-9.2,5.2) H4(-8.4,5.2) H5(-7.6,5.2) H6(-6.8,5.2) H7(-6,5.2) H8(-5.2,5.2) H9(-4.4,5.2) H10(-3.6,5.2) H11(-2.8,5.2) H12(-2,5.2) H13(-1.2,5.2) H14(-0.4,5.2) H15(0.4,5.2) H16(1.2,5.2) H17(2,5.2) H18(2.8,5.2) H19(3.6,5.2) H20(4.4,5.2) H21(5.2,5.2) H22(6,5.2) H23(6.8,5.2) H24(7.6,5.2) H25(8.4,5.2) H26(9.2,5.2) H27(10,5.2) H28(10.8,5.2) J1(-10.8,4.4) J2(-10,4.4) J3(-9.2,4.4) J4(-8.4,4.4) J5(-7.6,4.4) J6(-6.8,4.4) J7(-6,4.4) J8(-5.2,4.4) J9(-4.4,4.4) J10(-3.6,4.4) J11(-2.8,4.4) J12(-2,4.4) J13(-1.2,4.4) J14(-0.4,4.4) J15(0.4,4.4) J16(1.2,4.4) J17(2,4.4) J18(2.8,4.4) J19(3.6,4.4) J20(4.4,4.4) J21(5.2,4.4) J22(6,4.4) J23(6.8,4.4) J24(7.6,4.4) J25(8.4,4.4) J26(9.2,4.4) J27(10,4.4) J28(10.8,4.4) K1(-10.8,3.6) K2(-10,3.6) K3(-9.2,3.6) K4(-8.4,3.6) K5(-7.6,3.6) K6(-6.8,3.6) K7(-6,3.6) K8(-5.2,3.6) K9(-4.4,3.6) K10(-3.6,3.6) K11(-2.8,3.6) K12(-2,3.6) K13(-1.2,3.6) K14(-0.4,3.6) K15(0.4,3.6) K16(1.2,3.6) K17(2,3.6) K18(2.8,3.6) K19(3.6,3.6) K20(4.4,3.6) K21(5.2,3.6) K22(6,3.6) K23(6.8,3.6) K24(7.6,3.6) K25(8.4,3.6) K26(9.2,3.6) K27(10,3.6) K28(10.8,3.6) L1(-10.8,2.8) L2(-10,2.8) L3(-9.2,2.8) L4(-8.4,2.8) L5(-7.6,2.8) L6(-6.8,2.8) L7(-6,2.8) L8(-5.2,2.8) L9(-4.4,2.8) L10(-3.6,2.8) L11(-2.8,2.8) L12(-2,2.8) L13(-1.2,2.8) L14(-0.4,2.8) L15(0.4,2.8) L16(1.2,2.8) L17(2,2.8) L18(2.8,2.8) L19(3.6,2.8) L20(4.4,2.8) L21(5.2,2.8) L22(6,2.8) L23(6.8,2.8) L24(7.6,2.8) L25(8.4,2.8) L26(9.2,2.8) L27(10,2.8) L28(10.8,2.8) M1(-10.8,2) M2(-10,2) M3(-9.2,2) M4(-8.4,2) M5(-7.6,2) M6(-6.8,2) M7(-6,2) M8(-5.2,2) M9(-4.4,2) M10(-3.6,2) M11(-2.8,2) M12(-2,2) M13(-1.2,2) M14(-0.4,2) M15(0.4,2) M16(1.2,2) M17(2,2) M18(2.8,2) M19(3.6,2) M20(4.4,2) M21(5.2,2) M22(6,2) M23(6.8,2) M24(7.6,2) M25(8.4,2) M26(9.2,2) M27(10,2) M28(10.8,2) N1(-10.8,1.2) N2(-10,1.2) N3(-9.2,1.2) N4(-8.4,1.2) N5(-7.6,1.2) N6(-6.8,1.2) N7(-6,1.2) N8(-5.2,1.2) N9(-4.4,1.2) N10(-3.6,1.2) N11(-2.8,1.2) N12(-2,1.2) N13(-1.2,1.2) N14(-0.4,1.2) N15(0.4,1.2) N16(1.2,1.2) N17(2,1.2) N18(2.8,1.2) N19(3.6,1.2) N20(4.4,1.2) N21(5.2,1.2) N22(6,1.2) N23(6.8,1.2) N24(7.6,1.2) N25(8.4,1.2) N26(9.2,1.2) N27(10,1.2) N28(10.8,1.2) P1(-10.8,0.4) P2(-10,0.4) P3(-9.2,0.4) P4(-8.4,0.4) P5(-7.6,0.4) P6(-6.8,0.4) P7(-6,0.4) P8(-5.2,0.4) P9(-4.4,0.4) P10(-3.6,0.4) P11(-2.8,0.4) P12(-2,0.4) P13(-1.2,0.4) P14(-0.4,0.4) P15(0.4,0.4) P16(1.2,0.4) P17(2,0.4) P18(2.8,0.4) P19(3.6,0.4) P20(4.4,0.4) P21(5.2,0.4) P22(6,0.4) P23(6.8,0.4) P24(7.6,0.4) P25(8.4,0.4) P26(9.2,0.4) P27(10,0.4) P28(10.8,0.4) R1(-10.8,-0.4) R2(-10,-0.4) R3(-9.2,-0.4) R4(-8.4,-0.4) R5(-7.6,-0.4) R6(-6.8,-0.4) R7(-6,-0.4) R8(-5.2,-0.4) R9(-4.4,-0.4) R10(-3.6,-0.4) R11(-2.8,-0.4) R12(-2,-0.4) R13(-1.2,-0.4) R14(-0.4,-0.4) R15(0.4,-0.4) R16(1.2,-0.4) R17(2,-0.4) R18(2.8,-0.4) R19(3.6,-0.4) R20(4.4,-0.4) R21(5.2,-0.4) R22(6,-0.4) R23(6.8,-0.4) R24(7.6,-0.4) R25(8.4,-0.4) R26(9.2,-0.4) R27(10,-0.4) R28(10.8,-0.4) T1(-10.8,-1.2) T2(-10,-1.2) T3(-9.2,-1.2) T4(-8.4,-1.2) T5(-7.6,-1.2) T6(-6.8,-1.2) T7(-6,-1.2) T8(-5.2,-1.2) T9(-4.4,-1.2) T10(-3.6,-1.2) T11(-2.8,-1.2) T12(-2,-1.2) T13(-1.2,-1.2) T14(-0.4,-1.2) T15(0.4,-1.2) T16(1.2,-1.2) T17(2,-1.2) T18(2.8,-1.2) T19(3.6,-1.2) T20(4.4,-1.2) T21(5.2,-1.2) T22(6,-1.2) T23(6.8,-1.2) T24(7.6,-1.2) T25(8.4,-1.2) T26(9.2,-1.2) T27(10,-1.2) T28(10.8,-1.2) U1(-10.8,-2) U2(-10,-2) U3(-9.2,-2) U4(-8.4,-2) U5(-7.6,-2) U6(-6.8,-2) U7(-6,-2) U8(-5.2,-2) U9(-4.4,-2) U10(-3.6,-2) U11(-2.8,-2) U12(-2,-2) U13(-1.2,-2) U14(-0.4,-2) U15(0.4,-2) U16(1.2,-2) U17(2,-2) U18(2.8,-2) U19(3.6,-2) U20(4.4,-2) U21(5.2,-2) U22(6,-2) U23(6.8,-2) U24(7.6,-2) U25(8.4,-2) U26(9.2,-2) U27(10,-2) U28(10.8,-2) V1(-10.8,-2.8) V2(-10,-2.8) V3(-9.2,-2.8) V4(-8.4,-2.8) V5(-7.6,-2.8) V6(-6.8,-2.8) V7(-6,-2.8) V8(-5.2,-2.8) V9(-4.4,-2.8) V10(-3.6,-2.8) V11(-2.8,-2.8) V12(-2,-2.8) V13(-1.2,-2.8) V14(-0.4,-2.8) V15(0.4,-2.8) V16(1.2,-2.8) V17(2,-2.8) V18(2.8,-2.8) V19(3.6,-2.8) V20(4.4,-2.8) V21(5.2,-2.8) V22(6,-2.8) V23(6.8,-2.8) V24(7.6,-2.8) V25(8.4,-2.8) V26(9.2,-2.8) V27(10,-2.8) V28(10.8,-2.8) W1(-10.8,-3.6) W2(-10,-3.6) W3(-9.2,-3.6) W4(-8.4,-3.6) W5(-7.6,-3.6) W6(-6.8,-3.6) W7(-6,-3.6) W8(-5.2,-3.6) W9(-4.4,-3.6) W10(-3.6,-3.6) W11(-2.8,-3.6) W12(-2,-3.6) W13(-1.2,-3.6) W14(-0.4,-3.6) W15(0.4,-3.6) W16(1.2,-3.6) W17(2,-3.6) W18(2.8,-3.6) W19(3.6,-3.6) W20(4.4,-3.6) W21(5.2,-3.6) W22(6,-3.6) W23(6.8,-3.6) W24(7.6,-3.6) W25(8.4,-3.6) W26(9.2,-3.6) W27(10,-3.6) W28(10.8,-3.6) Y1(-10.8,-4.4) Y2(-10,-4.4) Y3(-9.2,-4.4) Y4(-8.4,-4.4) Y5(-7.6,-4.4) Y6(-6.8,-4.4) Y7(-6,-4.4) Y8(-5.2,-4.4) Y9(-4.4,-4.4) Y10(-3.6,-4.4) Y11(-2.8,-4.4) Y12(-2,-4.4) Y13(-1.2,-4.4) Y14(-0.4,-4.4) Y15(0.4,-4.4) Y16(1.2,-4.4) Y17(2,-4.4) Y18(2.8,-4.4) Y19(3.6,-4.4) Y20(4.4,-4.4) Y21(5.2,-4.4) Y22(6,-4.4) Y23(6.8,-4.4) Y24(7.6,-4.4) Y25(8.4,-4.4) Y26(9.2,-4.4) Y27(10,-4.4) Y28(10.8,-4.4)
CC0201
  rect 0.47x0.381 smd: 1(-0.343,0) 2(0.343,0)
CC0402_25
  round 0.635 smd: 1(-0.508,0) 2(0.508,0)
CC0603_NFM18PC
  rect 0.61x0.61 smd: 1(-0.8,0) 3(0.8,0)
  rect 0.406x1.702 smd: 2(0,0)
CC0603_OV
  oval 0.889x1.143 smd: 1(-0.762,0) 2(0.762,0)
CC0805_OV
  oval 0.889x1.524 smd: 1(-0.965,0) 2(0.965,0)
CC1206_OV
  oval 1.016x1.778 smd: 1(-1.524,0) 2(1.524,0)
CC3528-21
  rect 1.905x2.286 smd: 1(-1.714,0) 2(1.714,0)
CC7343-31
  rect 2.134x2.997 smd: 1(-3.251,0) 2(3.251,0)
CC_NFM41P_1806
  rect 1.295x1.219 smd: 1(-2.375,0) 3(2.375,0)
  rect 1.524x1.016 smd: 2A(0,-0.813) 2B(0,0.813)
CCE6P8X6P8
  rect 3.556x1.651 smd: 1(-2.35,0) 2(2.35,0)
CON_1X8_SKT_2P54_TH
  rect 1.702x1.702 hole 1.016: 1(0,0)
  round 1.702 hole 1.016: 2(0,-2.54) 3(0,-5.08) 4(0,-7.62) 5(0,-10.16) 6(0,-12.7) 7(0,-15.24) 8(0,-17.78)
CON_18P_USB3_RA_TH
  rect 1.219x1.219 hole 0.711: 1(0,0)
  round 1.219 hole 0.711: 2(0,-2.5) 3(0,-4.5) 4(0,-7) 5(1.5,-7.5) 6(1.5,-5.5) 7(1.5,-3.5) 8(1.5,-1.5) 9(1.5,0.5) 10(3.2,0) 11(3.2,-2.5) 12(3.2,-4.5) 13(3.2,-7) 14(4.7,-7.5) 15(4.7,-5.5) 16(4.7,-3.5) 17(4.7,-1.5) 18(4.7,0.5)
  round 2.946 hole 2.311: S1(-2,3.07) S2(3.68,3.07) S3(3.68,-10.07) S4(-2,-10.07)
CON_67_0P5_22X7P75_RA
  rect 1.194x2.743 smd: (-10.35,3.125) (10.35,3.125)
  round 0.254 hole 1.092 unplated: (-10,-1.375)
  round 0.254 hole 1.6 unplated: (10,-1.375)
  rect 0.305x1.549 smd: 1(-9.25,3.9) 2(-9,-3.65) 3(-8.75,3.9) 4(-8.5,-3.65) 5(-8.25,3.9) 6(-8,-3.65) 7(-7.75,3.9) 8(-7.5,-3.65) 9(-7.25,3.9) 10(-7,-3.65) 11(-6.75,3.9) 12(-6.5,-3.65) 13(-6.25,3.9) 14(-6,-3.65) 15(-5.75,3.9) 16(-5.5,-3.65) 17(-5.25,3.9) 18(-5,-3.65) 19(-4.75,3.9) 20(-4.5,-3.65) 21(-4.25,3.9) 22(-4,-3.65) 23(-3.75,3.9) 32(-1.5,-3.65) 33(-1.25,3.9) 34(-1,-3.65) 35(-0.75,3.9) 36(-0.5,-3.65) 37(-0.25,3.9) 38(0,-3.65) 39(0.25,3.9) 40(0.5,-3.65) 41(0.75,3.9) 42(1,-3.65) 43(1.25,3.9) 44(1.5,-3.65) 45(1.75,3.9) 46(2,-3.65) 47(2.25,3.9) 48(2.5,-3.65) 49(2.75,3.9) 50(3,-3.65) 51(3.25,3.9) 52(3.5,-3.65) 53(3.75,3.9) 54(4,-3.65) 55(4.25,3.9) 56(4.5,-3.65) 57(4.75,3.9) 58(5,-3.65) 59(5.25,3.9) 60(5.5,-3.65) 61(5.75,3.9) 62(6,-3.65) 63(6.25,3.9) 64(6.5,-3.65) 65(6.75,3.9) 66(7,-3.65) 67(7.25,3.9) 68(7.5,-3.65) 69(7.75,3.9) 70(8,-3.65) 71(8.25,3.9) 72(8.5,-3.65) 73(8.75,3.9) 74(9,-3.65) 75(9.25,3.9)
CON_DCJACK_063BH_TH_RA
  oval 1.778x4.293 hole 1.016x3.531: (-4.5,7) (4.5,7)
  round 0.254 hole 1.6 unplated: (0,9)
  oval 4.801x1.778 hole 4.039x1.016: 1(0,0)
  oval 4.089x1.778 hole 3.327x1.016: 2(0,6)
CON_RJ45_2X1_TH_RA
  round 0.254 hole 3.251 unplated: (-0.545,-5.26) (12.545,-5.26)
  rect 1.397x1.397 hole 0.889: 1(0,0)
  round 1.397 hole 0.889: 2(2,0) 3(4,0) 4(6,0) 5(8,0) 6(10,0) 7(12,0) 8(1,2.54) 9(3,2.54) 10(5,2.54) 11(7,2.54) 12(9,2.54) 13(11,2.54) 14(0,10.41) 15(2,10.41) 16(4,10.41) 17(6,10.41) 18(8,10.41) 19(10,10.41) 20(12,10.41) 21(1,12.95) 22(3,12.95) 23(5,12.95) 24(7,12.95) 25(9,12.95) 26(11,12.95)
  round 1.524 hole 1.016: 27(0.055,-8.1) 28(2.085,-8.1) 29(9.915,-8.1) 30(11.945,-8.1) 31(0.545,16.76) 32(3.085,16.76) 33(8.915,16.76) 34(11.455,16.76)
  round 2.108 hole 1.6: S1(-2.395,6.53) S2(14.395,6.53) S3(-2.395,-9.83) S4(14.395,-9.83)
CON_SDCARD_95220
  rect 0.813x1.499 smd: 1(-1.94,3.267) 2(-0.84,2.867) 3(0.26,3.267) 4(1.36,3.468) 5(2.46,3.267) 6(3.56,3.468) 7(4.66,3.267) 8(5.76,3.267)
  rect 0.991x0.94 smd: 9(3.56,-7.368)
  rect 1.397x1.905 smd: SH1(6.6,6.187) SH2(-6.6,7.107)
  rect 1.295x1.422 smd: SH3(4.95,-7.092) SH4(-0.75,-7.092)
CON_TSM_20M_2P54_SM
  rect 1.27x3.683 smd: 1(-11.43,-2.475) 2(-11.43,2.475) 3(-8.89,-2.475) 4(-8.89,2.475) 5(-6.35,-2.475) 6(-6.35,2.475) 7(-3.81,-2.475) 8(-3.81,2.475) 9(-1.27,-2.475) 10(-1.27,2.475) 11(1.27,-2.475) 12(1.27,2.475) 13(3.81,-2.475) 14(3.81,2.475) 15(6.35,-2.475) 16(6.35,2.475) 17(8.89,-2.475) 18(8.89,2.475) 19(11.43,-2.475) 20(11.43,2.475)
CON_USB_5F_0P65_SM_RA_B
  rect 0.457x1.092 smd: 1(-1.3,4.67) 2(-0.65,4.67) 3(0,4.67) 4(0.65,4.67) 5(1.3,4.67)
  oval 1.194x2.108 hole 0.61x1.524: S1(-4.95,4.15) S2(4.95,4.15)
  oval 1.194x2.413 hole 0.61x1.803: S3(-4.95,0.15) S4(4.95,0.15)
DIODE_BIDIR_0402
  rect 0.559x0.61 smd: 1(-0.425,0) 2(0.425,0)
FUSE_3P4X1P8
  rect 0.991x1.803 smd: 1(-1.25,0) 2(1.25,0)
HDR1X2_50MIL
  rect 1.092x1.092 hole 0.711: 1(0,0)
  round 1.092 hole 0.711: 2(0,-1.27)
HDR102
  rect 1.524x1.524 hole 1.016: 1(0,0)
  round 1.524 hole 1.016: 2(0,-2.54)
HDR103
  rect 1.524x1.524 hole 1.016: 1(0,0)
  round 1.524 hole 1.016: 2(0,-2.54) 3(0,-5.08)
HDR106_TH_TSW
  rect 1.524x1.524 hole 1.041: 1(0,0)
  round 1.524 hole 1.041: 2(0,-2.54) 3(0,-5.08) 4(0,-7.62) 5(0,-10.16) 6(0,-12.7)
HDR205_10M_50_SM_K
  rect 0.737x2.794 smd: 1(-2.54,-2.032) 2(-2.54,2.032) 3(-1.27,-2.032) 4(-1.27,2.032) 5(0,-2.032) 6(0,2.032) 7(1.27,-2.032) 8(1.27,2.032) 9(2.54,-2.032) 10(2.54,2.032)
IND2_4P3SQ_XFL4020
  rect 0.965x3.404 smd: 1(-1.185,0) 2(1.185,0)
IND2_744308033
  rect 2.591x3.607 smd: 1(0,3.8) 2(0,-3.8)
IND2_XAL60XX_102
  rect 1.422x5.486 smd: 1(-2.019,0) 2(2.019,0)
IND4_7X13_SM
  rect 2.057x3.988 smd: 1(-2.25,6) 2(2.25,6) 3(2.25,-6) 4(-2.25,-6)
IND2520
  rect 0.914x2.21 smd: 1(-1.05,0) 2(1.05,0)
IND_0402
  round 0.635 smd: 1(-0.508,0) 2(0.508,0)
IND_NFE31P
  rect 0.991x1.803 smd: 1(-1.6,0) 3(1.6,0)
  rect 1.194x1.803 smd: 2(0,0)
JUMP1X4-6040
  rect 1.524x1.524 hole 1.016: 1(0,0)
  round 1.524 hole 1.016: 2(2.54,0) 3(5.08,0) 4(7.62,0)
JUMP1X8-6040
  rect 1.524x1.524 hole 1.016: 1(0,0)
  round 1.524 hole 1.016: 2(0,-2.54) 3(0,-5.08) 4(0,-7.62) 5(0,-10.16) 6(0,-12.7) 7(0,-15.24) 8(0,-17.78)
LED_0603
  rect 0.838x0.787 smd: A(-0.775,0) C(0.775,0)
LED_QUAD_2P54_TH
  rect 1.397x1.397 hole 0.889: 1(0,0)
  round 1.397 hole 0.889: 2(0,2.54) 3(-2.54,0) 4(-2.54,2.54) 5(-5.08,0) 6(-5.08,2.54) 7(-7.62,0) 8(-7.62,2.54)
MH_C256-165T
  round 6.502 hole 4.191: 1(0,0)
MSOP_10_0P5_3X3
  rect 1.372x0.279 smd: 1(-2.24,1) 2(-2.24,0.5) 3(-2.24,0) 4(-2.24,-0.5) 5(-2.24,-1) 6(2.24,-1) 7(2.24,-0.5) 8(2.24,0) 9(2.24,0.5) 10(2.24,1)
PMC_MECH_HOLE
  round 6.198 hole 3.2: 1(0,0)
QFN16_0P5_3X3_EP_4MP
  rect 0.381x0.381 smd: (-1.312,1.312) (-1.312,-1.312) (1.312,1.312) (1.312,-1.312)
  rect 0.711x0.254 smd: 1(-1.4,0.75) 2(-1.4,0.25) 3(-1.4,-0.25) 4(-1.4,-0.75) 9(1.4,-0.75) 10(1.4,-0.25) 11(1.4,0.25) 12(1.4,0.75)
  rect 0.254x0.711 smd: 5(-0.75,-1.4) 6(-0.25,-1.4) 7(0.25,-1.4) 8(0.75,-1.4) 13(0.75,1.4) 14(0.25,1.4) 15(-0.25,1.4) 16(-0.75,1.4)
  rect 1.448x1.448 smd: 17(0,0)
QFN20_3X3MM_B
  rect 0.305x0.305 smd: 1(-1.25,1.25) 6(-1.25,-1.25) 11(1.25,-1.25) 16(1.25,1.25)
  rect 0.889x0.305 smd: 2(-1.55,0.75) 3(-1.55,0.25) 4(-1.55,-0.25) 5(-1.55,-0.75) 12(1.55,-0.75) 13(1.55,-0.25) 14(1.55,0.25) 15(1.55,0.75)
  rect 0.305x0.889 smd: 7(-0.75,-1.55) 8(-0.25,-1.55) 9(0.25,-1.55) 10(0.75,-1.55) 17(0.75,1.55) 18(0.25,1.55) 19(-0.25,1.55) 20(-0.75,1.55)
  rect 1.803x1.803 smd: 21(0,0)
QFN24_4X4MM_4EP
  rect 0.381x0.381 smd: (-1.813,1.813) (-1.813,-1.813) (1.813,1.813) (1.813,-1.813)
  rect 0.711x0.254 smd: 1(-1.9,1.25) 2(-1.9,0.75) 3(-1.9,0.25) 4(-1.9,-0.25) 5(-1.9,-0.75) 6(-1.9,-1.25) 13(1.9,-1.25) 14(1.9,-0.75) 15(1.9,-0.25) 16(1.9,0.25) 17(1.9,0.75) 18(1.9,1.25)
  rect 0.254x0.711 smd: 7(-1.25,-1.9) 8(-0.75,-1.9) 9(-0.25,-1.9) 10(0.25,-1.9) 11(0.75,-1.9) 12(1.25,-1.9) 19(1.25,1.9) 20(0.75,1.9) 21(0.25,1.9) 22(-0.25,1.9) 23(-0.75,1.9) 24(-1.25,1.9)
  rect 1.118x1.118 smd: 25(-0.662,0.662) 26(0.662,0.662) 27(-0.662,-0.662) 28(0.662,-0.662)
QFN40_0P5_6X6_2P6EP
  oval 0.508x0.305 smd: 1(-2.76,2.25) 10(-2.76,-2.25) 21(2.76,-2.25) 30(2.76,2.25)
  rect 0.508x0.305 smd: 2(-2.76,1.75) 3(-2.76,1.25) 4(-2.76,0.75) 5(-2.76,0.25) 6(-2.76,-0.25) 7(-2.76,-0.75) 8(-2.76,-1.25) 9(-2.76,-1.75) 22(2.76,-1.75) 23(2.76,-1.25) 24(2.76,-0.75) 25(2.76,-0.25) 26(2.76,0.25) 27(2.76,0.75) 28(2.76,1.25) 29(2.76,1.75)
  oval 0.305x0.508 smd: 11(-2.25,-2.76) 20(2.25,-2.76) 31(2.25,2.76) 40(-2.25,2.76)
  rect 0.305x0.508 smd: 12(-1.75,-2.76) 13(-1.25,-2.76) 14(-0.75,-2.76) 15(-0.25,-2.76) 16(0.25,-2.76) 17(0.75,-2.76) 18(1.25,-2.76) 19(1.75,-2.76) 32(1.75,2.76) 33(1.25,2.76) 34(0.75,2.76) 35(0.25,2.76) 36(-0.25,2.76) 37(-0.75,2.76) 38(-1.25,2.76) 39(-1.75,2.76)
  rect 2.591x2.591 smd: 41(0,0)
QFN56_0P5_8P1X8P1_EP5P1
  rect 0.305x0.305 smd: (-3.73,3.73) (-3.73,-3.73) (3.73,3.73) (3.73,-3.73)
  oval 0.914x0.279 smd: 1(-3.922,3.25) 2(-3.922,2.75) 3(-3.922,2.25) 4(-3.922,1.75) 5(-3.922,1.25) 6(-3.922,0.75) 7(-3.922,0.25) 8(-3.922,-0.25) 9(-3.922,-0.75) 10(-3.922,-1.25) 11(-3.922,-1.75) 12(-3.922,-2.25) 13(-3.922,-2.75) 14(-3.922,-3.25) 29(3.922,-3.25) 30(3.922,-2.75) 31(3.922,-2.25) 32(3.922,-1.75) 33(3.922,-1.25) 34(3.922,-0.75) 35(3.922,-0.25) 36(3.922,0.25) 37(3.922,0.75) 38(3.922,1.25) 39(3.922,1.75) 40(3.922,2.25) 41(3.922,2.75) 42(3.922,3.25)
  oval 0.279x0.914 smd: 15(-3.25,-3.922) 16(-2.75,-3.922) 17(-2.25,-3.922) 18(-1.75,-3.922) 19(-1.25,-3.922) 20(-0.75,-3.922) 21(-0.25,-3.922) 22(0.25,-3.922) 23(0.75,-3.922) 24(1.25,-3.922) 25(1.75,-3.922) 26(2.25,-3.922) 27(2.75,-3.922) 28(3.25,-3.922) 43(3.25,3.922) 44(2.75,3.922) 45(2.25,3.922) 46(1.75,3.922) 47(1.25,3.922) 48(0.75,3.922) 49(0.25,3.922) 50(-0.25,3.922) 51(-0.75,3.922) 52(-1.25,3.922) 53(-1.75,3.922) 54(-2.25,3.922) 55(-2.75,3.922) 56(-3.25,3.922)
  rect 5.08x5.08 smd: 57(0,0)
RC0201
  rect 0.47x0.381 smd: 1(-0.343,0) 2(0.343,0)
RC0402_25
  round 0.635 smd: 1(-0.508,0) 2(0.508,0)
RC1206_OV
  oval 1.016x1.778 smd: 1(-1.524,0) 2(1.524,0)
RES4_7P1X6P9_SM
  rect 2.438x5.613 smd: 1(-2.48,-0.89) 4(2.48,-0.89)
  rect 2.438x0.889 smd: 2(-2.48,3.245) 3(2.48,3.245)
SC70-5
  rect 0.406x0.813 smd: 1(-0.65,-1.079) 2(0,-1.079) 3(0.65,-1.079) 4(0.65,1.079) 5(-0.65,1.079)
SKT_BAT_225X886_3V
  rect 1.651x1.651 hole 1.016: 1(0,0)
  round 1.651 hole 1.016: 2(10,0) 3(5,3.47)
SO8_1P27_4X5
  rect 1.6x0.61 smd: 1(-2.7,1.905) 2(-2.7,0.635) 3(-2.7,-0.635) 4(-2.7,-1.905) 5(2.7,-1.905) 6(2.7,-0.635) 7(2.7,0.635) 8(2.7,1.905)
SO16W
  rect 2.184x0.61 smd: 1(-4.826,4.445) 2(-4.826,3.175) 3(-4.826,1.905) 4(-4.826,0.635) 5(-4.826,-0.635) 6(-4.826,-1.905) 7(-4.826,-3.175) 8(-4.826,-4.445) 9(4.826,-4.445) 10(4.826,-3.175) 11(4.826,-1.905) 12(4.826,-0.635) 13(4.826,0.635) 14(4.826,1.905) 15(4.826,3.175) 16(4.826,4.445)
SO20_1P27_7P6X12P95
  rect 1.778x0.61 smd: 1(-4.738,5.715) 2(-4.738,4.445) 3(-4.738,3.175) 4(-4.738,1.905) 5(-4.738,0.635) 6(-4.738,-0.635) 7(-4.738,-1.905) 8(-4.738,-3.175) 9(-4.738,-4.445) 10(-4.738,-5.715) 11(4.738,-5.715) 12(4.738,-4.445) 13(4.738,-3.175) 14(4.738,-1.905) 15(4.738,-0.635) 16(4.738,0.635) 17(4.738,1.905) 18(4.738,3.175) 19(4.738,4.445) 20(4.738,5.715)
SOD123
  rect 1.016x1.27 smd: A(1.651,0) C(-1.651,0)
SOT23-40X40
  rect 1.016x1.016 smd: 1(-0.94,-1.003) 2(0.94,-1.003) 3(0,1.003)
SOT143B
  rect 0.991x0.61 smd: 1(-0.75,-1)
  rect 0.508x0.61 smd: 2(0.95,-1) 3(0.95,1) 4(-0.95,1)
SOT323_3
  rect 0.406x0.991 smd: 1(0.65,-1.06) 2(-0.65,-1.06) 3(0,1.06)
SOT-363_0P65_SMT
  rect 0.762x0.381 smd: 1(-1.085,0.65) 2(-1.085,0) 3(-1.085,-0.65) 4(1.085,-0.65) 5(1.085,0) 6(1.085,0.65)
SSOP8_DCU
  rect 0.279x1.219 smd: 1(-0.75,-1.499) 2(-0.25,-1.499) 3(0.25,-1.499) 4(0.75,-1.499) 5(0.75,1.499) 6(0.25,1.499) 7(-0.25,1.499) 8(-0.75,1.499)
SW2_4P45_4X3_SM
  rect 1.041x2.007 smd: 1(-2.225,0) 2(2.225,0)
SW_DIP20_10POS_SM
  rect 0.762x1.27 smd: 1(-5.725,-3.81) 2(-4.455,-3.81) 3(-3.185,-3.81) 4(-1.915,-3.81) 5(-0.635,-3.81) 6(0.635,-3.81) 7(1.905,-3.81) 8(3.175,-3.81) 9(4.445,-3.81) 10(5.715,-3.81) 11(5.715,3.81) 12(4.445,3.81) 13(3.175,3.81) 14(1.905,3.81) 15(0.635,3.81) 16(-0.635,3.81) 17(-1.915,3.81) 18(-3.185,3.81) 19(-4.455,3.81) 20(-5.725,3.81)
TP_PTH
  round 0.889 hole 0.457: 1(0,0)
TP_TH_063
  round 2.311 hole 1.6: 1(0,0)
TPAD_020
  round 0.508 smd: 1(0,0)
TSSOP8_A
  rect 1.448x0.457 smd: 1(-2.15,0.975) 2(-2.15,0.325) 3(-2.15,-0.325) 4(-2.15,-0.975) 5(2.15,-0.975) 6(2.15,-0.325) 7(2.15,0.325) 8(2.15,0.975)
TSSOP16
  rect 1.524x0.305 smd: 1(-3.048,2.276) 2(-3.048,1.626) 3(-3.048,0.975) 4(-3.048,0.325) 5(-3.048,-0.325) 6(-3.048,-0.975) 7(-3.048,-1.626) 8(-3.048,-2.276) 9(3.048,-2.276) 10(3.048,-1.626) 11(3.048,-0.975) 12(3.048,-0.325) 13(3.048,0.325) 14(3.048,0.975) 15(3.048,1.626) 16(3.048,2.276)
unnamed#2
  round 1.524 smd: (0,0)
unnamed#3
  round 1.626 hole 0.965: (0,0) (0,-5.08)
UQFN10_0P4_1P45X1P85
  rect 0.686x0.229 smd: 1(-0.527,0.2)
  rect 0.584x0.229 smd: 2(-0.578,-0.2) 6(0.578,-0.2) 7(0.578,0.2)
  rect 0.229x0.584 smd: 3(-0.4,-0.778) 4(0,-0.778) 5(0.4,-0.778) 8(0.4,0.778) 9(0,0.778) 10(-0.4,0.778)
VFBGA63_0P8_9X11
  round 0.356 smd: A1(-3.6,4.4) A2(-2.8,4.4) A9(2.8,4.4) A10(3.6,4.4) B1(-3.6,3.6) B9(2.8,3.6) B10(3.6,3.6) C3(-2,2.8) C4(-1.2,2.8) C5(-0.4,2.8) C6(0.4,2.8) C7(1.2,2.8) C8(2,2.8) D3(-2,2) D4(-1.2,2) D5(-0.4,2) D6(0.4,2) D7(1.2,2) D8(2,2) E3(-2,1.2) E4(-1.2,1.2) E5(-0.4,1.2) E6(0.4,1.2) E7(1.2,1.2) E8(2,1.2) F3(-2,0.4) F4(-1.2,0.4) F5(-0.4,0.4) F6(0.4,0.4) F7(1.2,0.4) F8(2,0.4) G3(-2,-0.4) G4(-1.2,-0.4) G5(-0.4,-0.4) G6(0.4,-0.4) G7(1.2,-0.4) G8(2,-0.4) H3(-2,-1.2) H4(-1.2,-1.2) H5(-0.4,-1.2) H6(0.4,-1.2) H7(1.2,-1.2) H8(2,-1.2) J3(-2,-2) J4(-1.2,-2) J5(-0.4,-2) J6(0.4,-2) J7(1.2,-2) J8(2,-2) K3(-2,-2.8) K4(-1.2,-2.8) K5(-0.4,-2.8) K6(0.4,-2.8) K7(1.2,-2.8) K8(2,-2.8) L1(-3.6,-3.6) L2(-2.8,-3.6) L9(2.8,-3.6) L10(3.6,-3.6) M1(-3.6,-4.4) M2(-2.8,-4.4) M9(2.8,-4.4) M10(3.6,-4.4)
WLCSP6_0P5_0P98X1P48
  round 0.254 smd: A1(-0.25,0.5) A2(0.25,0.5) B1(-0.25,0) B2(0.25,0) C1(-0.25,-0.5) C2(0.25,-0.5)
WLCSP12_0P4_1P38X1P68MM_SMDP
  round 0.254 smd: A1(-0.4,0.6) A2(0,0.6) A3(0.4,0.6) B1(-0.4,0.2) B2(0,0.2) B3(0.4,0.2) C1(-0.4,-0.2) C2(0,-0.2) C3(0.4,-0.2) D1(-0.4,-0.6) D2(0,-0.6) D3(0.4,-0.6)
XSON7_0P5_2P2X1P2
  rect 0.533x0.203 smd: 1(-0.415,0.75) 2(-0.415,0.25) 3(-0.415,-0.25) 4(-0.415,-0.75) 5(0.415,-0.5) 6(0.415,0) 7(0.415,0.5)
XSON10_0P5_1P1X2P6MM
  rect 0.711x0.254 smd: 1(-0.457,1) 2(-0.457,0.5) 3(-0.457,0) 4(-0.457,-0.5) 5(-0.457,-1) 6(0.457,-1) 7(0.457,-0.5) 8(0.457,0) 9(0.457,0.5) 10(0.457,1)
XSON_8P
  rect 0.305x0.61 smd: 1(-0.75,-0.417) 2(-0.25,-0.417) 3(0.25,-0.417) 4(0.75,-0.417) 5(0.75,0.417) 6(0.25,0.417) 7(-0.25,0.417) 8(-0.75,0.417)

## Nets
1V0_F104: C787.1 C851.1 C852.1 C853.1 C854.1 C855.1 C1454.1 C1455.1 C1475.1 C1476.1 C1495.1 FL19.1 L531.1 U123.E5 U123.E7 U123.E10 U123.E13 U123.E15 U123.E17 U123.E19 U123.E21 U123.E23 U123.E25 U561.3
1V0_QSG: C788.1 C1000.1 C1001.1 C1003.1 C1004.1 C1005.1 C1007.1 C1008.1 C1456.1 FL19.3(OUT_IN) U123.E1 U123.E11 U123.E14 U123.E16 U123.E28 U123.E30 U123.E32 U123.E34 U123.E36
1V35: C277.1 C1524.1 C1525.1 C1526.1 FL8.1 L533.1 U561.13
2V5: C160.1 C161.1 C369.1 C789.1 C1015.1 C1016.1 C1017.1 C1018.1 C1019.1 C1020.1 C1103.1 C1384.1 C1408.1 C1432.1 C1457.1 C1458.1 C1536.1 C1537.1 C1538.1 C1579.1 FL18.3(OUT_IN) FL22.1 L537.1 R651.1 R654.2 R657.2 R658.2 R659.2 R871.2 R872.2 U14.W6 U15.B1 U15.R9 U16.B1 U16.R9 U17.B1 U17.R9 U18.B1 U18.R9 U123.E3 U123.E4 U123.E6 U123.E8 U123.E9 U123.E12 U123.E18 U123.E20 U123.E22 U123.E24 U123.E26 U561.38 U565.B1 U565.R9
2V5_LED: C729.1 C1104.1 FL22.3(OUT_IN) P1.28 P1.29 P1.32 P1.33 P2.28 P2.29 P2.32 P2.33
2V5_QSG: C798.1 C1009.1 C1010.1 C1011.1 C1013.1 C1459.1 FL18.1 U123.E27 U123.E29 U123.E31 U123.E33 U123.E35 U123.E37
3V3: C278.1 C298.1 C299.1 C300.1 C301.1 C302.1 C438.1 C450.1 C452.1 C454.1 C488.1 C1174.1 C1255.1 C1256.1 C1258.1 C1259.1 C1271.1 C1272.1 C1282.1 C1283.1 C1298.1 C1299.1 C1302.1 C1304.1 C1305.1 C1307.1 C1309.1 C1310.1 C1313.1 C1315.1 C1316.1 C1319.1 C1327.1 C1334.1 C1337.1 C1338.1 C1339.1 C1340.1 C1341.1 C1434.1 C1435.1 C1443.1 C1444.1 C1445.1 C1446.1 C1447.1 C1448.1 C1449.1 C1450.1 C1451.1 C1452.1 C1453.1 C1464.1 C1465.1 C1466.1 C1470.1 C1481.1 C1489.1 C1490.1 C1491.1 C1492.1 C1493.1 C1494.1 C1542.1 C1544.1 C1547.1 C1548.1 C1549.1 C1555.1 D2.A D509.2 D509.4 D509.6 FL5.1 FL28.3(OUT_IN) FL30.3(OUT_IN) J46.2 J46.4 J46.72 J46.74 J52.2 J52.4 J52.72 J52.74 J55.4 J56.7 J66.1 J73.1 L516.2 R5.1 R10.1 R66.1 R245.1 R666.1 R667.1 R668.1 R669.2 R739.1 R742.2 R743.2 R744.2 R748.1 R749.1 R750.1 R751.1 R752.1 R753.1 R754.1 R755.1 R756.1 R757.1 R758.1 R777.1 R778.1 R801.2 R803.1 R804.1 R805.1 R828.1 R829.1 R830.1 R831.1 R832.1 R833.1 R834.1 R840.2 R843.1 R851.1 R852.1 R853.1 R854.1 R855.1 R856.1 R857.1 R858.2 R864.1 R869.1 R878.1 R900.1 R901.1 R904.1 R920.1 R922.2 R923.2 R927.1 R928.1 R929.1 R931.2 R934.1 R936.1 R940.1 R944.1 R946.1 TVS1.1 U14.N7 U14.P7 U14.R6 U24.5(VCC) U28.1(VDD) U35.1 U36.1 U37.8(VCCB) U54.A1(VCC) U523.20 U524.2 U524.8 U525.1 U525.2 U525.13 U525.16 U530.5 U535.5 U536.6 U536.7 U538.8(VCC) U539.1 U540.1 U547.5 U548.7(VCCB) U549.1 U551.5 U554.9(VCC) U555.1 U558.6 U561.4 U561.7 U561.8 U561.11 U561.17 U561.26 U561.27 U561.32 U561.35 U561.37 U561.50 U561.54 U562.5 U566.5
3V3_EN: R906.2 R907.1 U560.17
5V0: C19.2 C20.1 C21.1 C22.1 C457.1 C1320.1 C1329.1 J57.7 L515.2 R7.2 U40.B1 U40.B2 U40.C1(VINT3) U550.B1 U550.B2 U550.C1(VINT3)
12V0: C5.1 C12.1 C14.1 C30.1 C31.1 C32.1 C1330.1 C1345.1 C1587.1 FL2.1 FL31.1 FL32.1 J75.1 L2.2
12V0_FILTERED_PS_V1V0: C24.1 C25.1 C26.1 C27.1 C28.1 FL32.3(OUTPUT) R13.1 U557.C2 U557.C5 U557.C6 U557.D1 U557.D2 U557.D5 U557.D6
12V0_FILTERED_PS_V3V3: C1346.1 C1347.1 C1348.1 C1468.1 C1469.1 C1581.1 FL31.3(OUTPUT) R906.1 U560.4 U560.5 U560.6 U560.13 U560.14 U560.15(VIN6)
12V0_FILTERED_PS_V5V0: C1331.1 C1332.1 FL2.3(OUTPUT) U1.9 U1.10
12V0_IN: F2.1 J1.1
12V0_IN_GND: C29.2 D6.A J1.2 L2.4
12V0_PS_F: C29.1 D6.C(CATHODE) F2.2 L2.1
AVDD_CGA1: C230.1 C231.1 C933.1 R91.2 U14.H11
AVDD_CGA2: C235.1 C236.1 C934.1 R93.2 U14.H10
AVDD_DDR1: C245.1 C246.1 C936.1 R97.2 U14.R21
AVDD_PLAT: C240.1 C243.1 C935.1 R95.2 U14.H9
AVDD_SRDS1_PLL1: C232.1 C233.1 C234.1 R92.1 U14.AA11
AVDD_SRDS1_PLL2: C237.1 C238.1 C239.1 R94.1 U14.AB6
AVDD_SRDS2_PLL1: C241.1 C242.1 C244.1 R96.1 U14.AB15
AVDD_SRDS2_PLL2: C247.1 C248.1 C249.1 R98.1 U14.AA16
